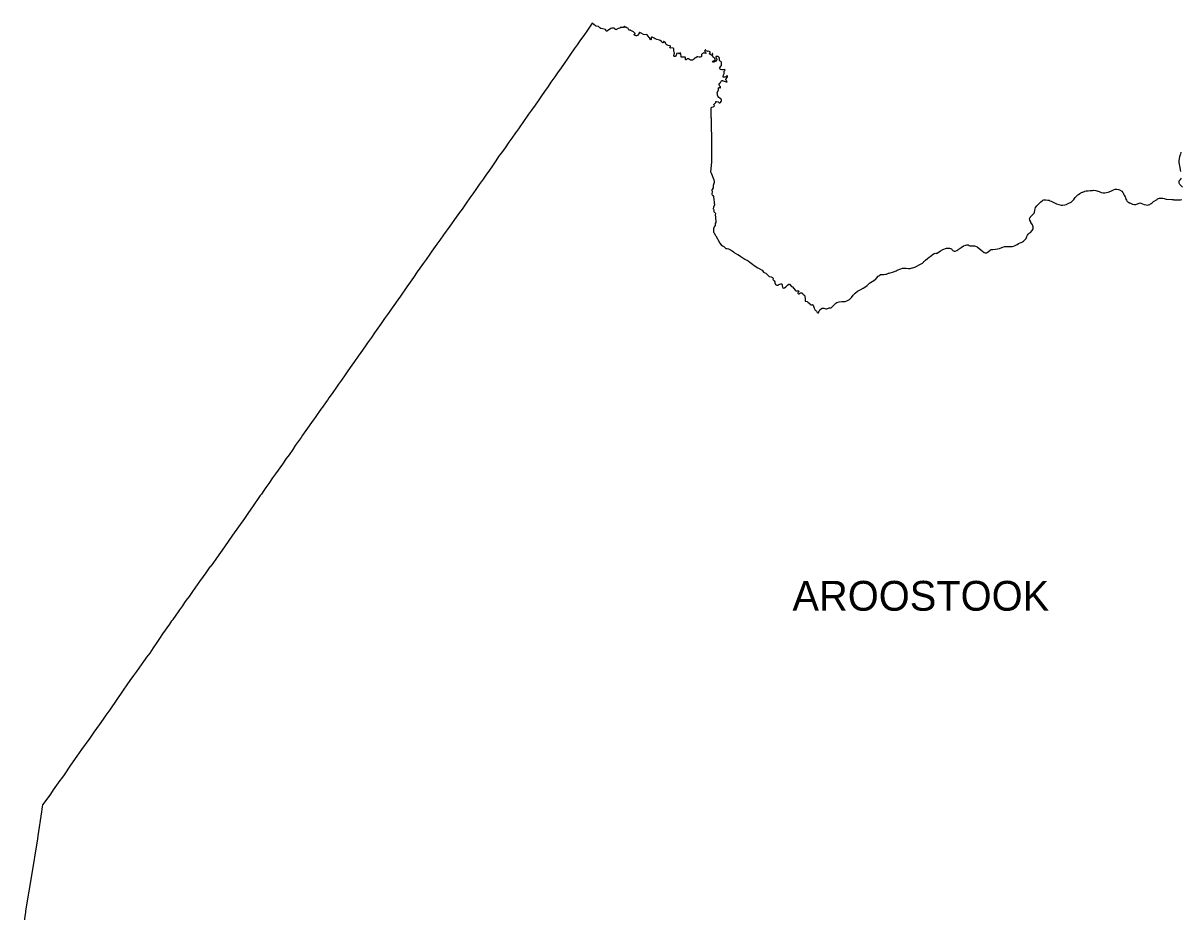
# Model space of a CAD drawing. Extents: x 1104458 to 2179854, y 15641624 to 17244911.
# Drawn here: x 1383254 to 1793637, y 16929881 to 17244911 of the extents above; entities that cross this region are included whole.
import ezdxf

# ---------------------------------------------------------------- set-up
doc = ezdxf.new("R2010")
doc.units = 0
doc.layers.add('ANNOTATION', color=7, linetype='Continuous')
doc.layers.add('CO BORDER', color=7, linetype='Continuous')

msp = doc.modelspace()

# ---------------------------------------------------------------- linework, layer by layer
at = {"layer": 'CO BORDER'}
for points in [[(1627164, 17211339), (1627163, 17214594), (1627155, 17214935), (1627355, 17215141), (1627889, 17215240), (1628089, 17215342), (1628197, 17215466), (1628272, 17215617), (1628214, 17215890), (1628123, 17216073), (1628106, 17216175), (1628173, 17216241), (1628515, 17216523), (1628748, 17216831), (1628823, 17217084), (1628999, 17217140), (1628990, 17217182), (1629615, 17217048), (1629707, 17216933), (1629715, 17216848), (1629957, 17216690), (1630107, 17216664), (1630240, 17216706), (1630473, 17216841), (1630649, 17217113), (1630774, 17217546), (1630757, 17217671), (1630699, 17217897), (1630641, 17218006), (1630225, 17218363), (1629883, 17218563), (1629542, 17219082), (1629409, 17219416), (1629392, 17219541), (1629359, 17219600), (1629334, 17219818), (1629259, 17220051), (1629276, 17220274), (1629326, 17220333), (1629685, 17221209), (1629794, 17221590), (1629794, 17221974), (1629927, 17222092), (1630069, 17222082), (1630269, 17221967), (1630444, 17221974), (1630452, 17222217), (1630402, 17222299), (1630211, 17222542), (1630103, 17222732), (1630020, 17223240), (1630045, 17223365), (1630012, 17223418), (1630070, 17223608), (1630420, 17223851), (1630629, 17224143), (1630637, 17224225), (1630654, 17224300), (1630812, 17224484), (1630996, 17224549), (1631187, 17224556), (1631362, 17224464), (1632412, 17224064), (1632695, 17224064), (1632795, 17224129), (1632754, 17224339), (1632504, 17224599), (1632371, 17224891), (1632396, 17225005), (1632471, 17225147), (1632813, 17225589), (1632972, 17225849), (1632972, 17226049), (1632930, 17226114), (1632822, 17226190), (1632722, 17226190), (1632589, 17226124), (1632355, 17225881), (1632138, 17225773), (1631938, 17225731), (1631622, 17225747), (1631438, 17225822), (1631372, 17225908), (1631364, 17226249), (1631464, 17226515), (1631539, 17226639), (1631664, 17226774), (1631722, 17226974), (1631723, 17227299), (1631715, 17227722), (1631781, 17227857), (1632048, 17228240), (1632023, 17228355), (1631949, 17228431), (1631349, 17228408), (1631040, 17228365), (1630873, 17228375), (1630473, 17228467), (1630299, 17228549), (1630165, 17228759), (1630149, 17228959), (1630199, 17229126), (1630599, 17229717), (1630699, 17229809), (1630775, 17229950), (1630800, 17230173), (1630776, 17231082), (1630742, 17231167), (1630601, 17231292), (1630326, 17231390), (1630184, 17231534), (1630151, 17231633), (1630134, 17232059), (1630060, 17232374), (1629935, 17232716), (1629769, 17232958), (1629627, 17233076), (1629427, 17233132), (1629085, 17233135), (1628844, 17233093), (1628760, 17233011), (1628760, 17232817), (1628810, 17232709), (1628993, 17232535), (1629076, 17232410), (1629135, 17232151), (1629126, 17231941), (1629059, 17231800), (1628809, 17231485), (1628300, 17231167), (1628059, 17231101), (1627851, 17231118), (1627675, 17231219), (1627684, 17231377), (1627767, 17231469), (1628209, 17231643), (1628418, 17231794), (1628534, 17231925), (1628568, 17232010), (1628568, 17232109), (1628468, 17232276), (1628460, 17232342), (1628243, 17232650), (1627993, 17232870), (1627669, 17233319), (1627661, 17233401), (1627627, 17233450), (1627719, 17233959), (1627561, 17234143), (1627444, 17234120), (1627411, 17233670), (1627344, 17233569), (1627269, 17233552), (1627077, 17233660), (1626852, 17233893), (1626678, 17233926), (1626586, 17233979), (1626811, 17234569), (1626837, 17234727), (1626778, 17234769), (1626170, 17234927), (1625886, 17234904), (1625753, 17234953), (1625362, 17235055), (1625279, 17235130), (1625154, 17235396), (1625045, 17235396), (1624962, 17235363), (1624862, 17235222), (1624837, 17235120), (1624853, 17235006), (1625170, 17234520), (1625236, 17234363), (1625194, 17234169), (1624536, 17234336), (1624361, 17234287), (1624228, 17234172), (1623994, 17234031), (1623744, 17233838), (1623677, 17233506), (1623677, 17233090), (1623627, 17232998), (1623193, 17232873), (1622943, 17232889), (1622460, 17232981), (1622168, 17232932), (1621702, 17232565), (1621276, 17232456), (1621193, 17232397), (1620884, 17232023), (1620542, 17231784), (1620326, 17231741), (1620084, 17231751), (1619876, 17231817), (1619093, 17232259), (1618885, 17232309), (1618643, 17232276), (1618301, 17231935), (1618151, 17231925), (1618068, 17231984), (1618010, 17232693), (1617927, 17232801), (1617727, 17232886), (1617018, 17232827), (1616560, 17232860), (1616518, 17232893), (1616452, 17233254), (1616444, 17233943), (1616411, 17234071), (1616203, 17234336), (1616128, 17234395), (1616044, 17234369), (1615994, 17234271), (1615944, 17234087), (1615844, 17234054), (1615677, 17234146), (1615569, 17234254), (1614953, 17234212), (1614836, 17234169), (1614827, 17233779), (1614794, 17233621), (1614735, 17233572), (1614727, 17233519), (1614535, 17233237), (1614427, 17233129), (1614319, 17233086), (1614177, 17233086), (1613952, 17233172), (1613868, 17233247), (1613852, 17233414), (1614161, 17234228), (1614153, 17234445), (1613962, 17234861), (1613895, 17235147), (1613937, 17235396), (1613887, 17235806), (1613821, 17235964), (1613729, 17236078), (1613637, 17236137), (1612796, 17236082), (1612579, 17236164), (1612521, 17236298), (1612521, 17236380), (1612671, 17236548), (1612704, 17236646), (1612688, 17236721), (1612596, 17236823), (1611896, 17237007), (1611413, 17237174), (1611313, 17237233), (1611197, 17237381), (1611114, 17237614), (1610897, 17237932), (1610539, 17238273), (1610389, 17238375), (1610280, 17238359), (1610222, 17238290), (1610164, 17238050), (1610072, 17237981), (1609947, 17237991), (1609855, 17238040), (1609838, 17238083), (1609755, 17238126), (1609709, 17238208), (1609534, 17238434), (1609019, 17238818), (1608786, 17238920), (1607928, 17239080), (1607295, 17239297), (1606954, 17239599), (1606488, 17239773), (1606205, 17239999), (1606130, 17240015), (1606005, 17239976), (1605921, 17239901), (1605879, 17239783), (1605870, 17239202), (1605836, 17239166), (1605836, 17239084), (1605794, 17239051), (1605619, 17239094), (1605404, 17239517), (1605354, 17239569), (1605279, 17239753), (1605196, 17239792), (1605179, 17239878), (1604864, 17240304), (1604415, 17240786), (1604282, 17240846), (1603648, 17240773), (1603190, 17240875), (1602299, 17241341), (1601900, 17241643), (1601708, 17241610), (1601148, 17240711), (1601006, 17240586), (1600647, 17240390), (1600531, 17240396), (1600214, 17240540), (1599989, 17240672), (1599931, 17240741), (1599890, 17240823), (1599907, 17240914), (1599999, 17241023), (1600191, 17241088), (1600182, 17241206), (1600116, 17241380), (1599850, 17241649), (1599642, 17241800), (1598910, 17242135), (1598677, 17242309), (1598519, 17242368), (1598110, 17242411), (1597911, 17242535), (1597736, 17242962), (1597728, 17243113), (1597687, 17243172), (1597237, 17243205), (1597129, 17243306), (1597129, 17243398), (1597063, 17243447), (1596604, 17243516), (1596380, 17243690), (1596313, 17243674), (1596029, 17243398), (1595504, 17243326), (1595129, 17243418), (1594954, 17243395), (1594879, 17243326), (1594879, 17243287), (1594779, 17243152), (1594670, 17243093), (1594178, 17243027), (1593986, 17242955), (1593936, 17242880), (1593744, 17242739), (1593627, 17242604), (1593536, 17242565), (1593311, 17242630), (1593169, 17242716), (1593111, 17242798), (1592737, 17243106), (1592495, 17243175), (1592204, 17243175), (1591895, 17243100), (1591595, 17242978), (1590785, 17242420), (1590184, 17242096), (1590076, 17242096), (1589951, 17242164), (1589810, 17242322), (1589761, 17242548), (1589702, 17242630), (1588203, 17243034), (1587987, 17243044), (1587687, 17243277), (1587246, 17243687), (1586330, 17243831), (1586097, 17243916), (1584927, 17244911), (1584213, 17243864), (1583259, 17242417), (1581955, 17240557), (1580851, 17239012), (1579639, 17237217), (1578618, 17235778), (1577331, 17233915), (1576343, 17232520), (1575007, 17230608), (1573961, 17229121), (1572699, 17227294), (1571686, 17225899), (1570358, 17223960), (1569345, 17222501), (1568050, 17220696), (1567013, 17219151), (1565792, 17217425), (1564696, 17215863), (1563426, 17214108), (1562430, 17212605), (1561422, 17211211)], [(1561422, 17211211), (1561085, 17210742), (1558802, 17207471), (1557814, 17206076), (1556453, 17204095), (1555414, 17202717), (1554078, 17200771), (1553165, 17199469), (1551811, 17197592), (1550857, 17196070), (1549637, 17194344), (1548582, 17192838), (1547271, 17190978), (1546274, 17189659), (1544871, 17187687), (1543941, 17186303), (1542605, 17184439), (1541550, 17182986), (1540255, 17181071), (1539309, 17179687), (1538819, 17178981)], [(1627164, 17211339), (1627269, 17201254), (1627211, 17197881), (1627236, 17195574), (1626936, 17192175), (1627019, 17192093), (1627453, 17190886), (1627894, 17189951), (1628103, 17189360), (1628244, 17188819), (1628236, 17188429), (1628061, 17188028), (1627878, 17187320), (1627878, 17187044), (1627803, 17186535), (1627470, 17185971), (1627412, 17185794), (1627445, 17184961), (1627370, 17184564), (1627370, 17184278), (1627445, 17184088), (1627745, 17183780), (1628028, 17183438), (1628103, 17182162), (1628203, 17181680), (1628253, 17181047), (1628328, 17180755), (1628336, 17180554), (1628328, 17180456), (1627912, 17179633), (1627887, 17179147), (1627942, 17179006)], [(1793666, 17192300), (1793415, 17193596), (1793379, 17193898), (1793328, 17194072), (1793129, 17195053), (1793070, 17195269), (1793055, 17196112), (1793141, 17196962), (1793311, 17197681), (1793514, 17198373), (1793588, 17198481), (1793775, 17199141)], [(1794189, 17186762), (1793258, 17187687), (1793046, 17188202), (1793043, 17188537), (1793098, 17188993), (1793337, 17189321), (1793461, 17189455), (1793824, 17189990)], [(1715417, 17165165), (1715797, 17165425), (1716620, 17165927), (1717369, 17166265), (1717743, 17166350), (1718052, 17166350), (1718219, 17166317), (1718645, 17166061), (1718803, 17166012), (1719286, 17166028), (1719612, 17165989), (1719795, 17165940), (1720453, 17165927), (1720870, 17165835), (1721380, 17165562), (1722684, 17164578), (1723921, 17163656), (1724263, 17163532), (1724447, 17163499), (1724788, 17163551), (1725312, 17163804), (1726010, 17164431), (1726134, 17164522), (1726442, 17164657), (1726892, 17164703), (1726992, 17164686), (1727900, 17164749), (1729315, 17165087), (1730139, 17165372), (1730522, 17165549), (1731129, 17165743), (1732679, 17165726), (1733629, 17165753), (1733743, 17165763), (1733826, 17165795), (1734350, 17165874), (1734916, 17166061), (1735597, 17166422), (1736104, 17166760), (1736627, 17167019), (1737027, 17167141), (1737467, 17167383), (1737849, 17167636), (1738612, 17168341), (1738763, 17168581), (1739098, 17169227), (1739296, 17169703), (1739543, 17170070), (1739850, 17170415), (1740298, 17170743), (1740928, 17171370), (1741258, 17171947), (1741289, 17172265), (1741262, 17172656), (1741016, 17173361), (1740486, 17174234), (1740435, 17174444), (1740106, 17175074), (1740038, 17175507), (1740086, 17175809), (1740267, 17176166), (1740540, 17176485), (1740731, 17176629), (1741170, 17177098), (1741419, 17177298), (1741618, 17177584), (1741733, 17177918), (1741821, 17178483), (1741886, 17178676), (1741951, 17179060), (1742082, 17179526), (1742545, 17180139), (1743548, 17181111), (1743962, 17181521), (1744601, 17182059), (1744709, 17182134), (1745058, 17182279), (1745766, 17182282), (1746534, 17182144), (1746909, 17182105), (1747168, 17181980), (1747652, 17181809), (1749574, 17180894), (1750426, 17180592), (1751186, 17180381), (1751527, 17180397), (1751719, 17180374), (1752477, 17180522), (1752984, 17180656), (1753948, 17181070), (1754729, 17181467), (1755698, 17182454), (1756204, 17183100), (1757148, 17184072), (1757322, 17184206), (1757829, 17184524), (1758045, 17184610), (1758220, 17184738), (1758701, 17184990), (1758884, 17185039), (1759150, 17185174), (1759450, 17185243), (1759624, 17185345), (1760065, 17185479), (1760374, 17185515), (1760732, 17185499), (1761448, 17185581), (1762364, 17185643), (1762681, 17185696), (1763531, 17185591), (1764207, 17185377), (1764333, 17185305), (1764649, 17185177), (1764900, 17185098), (1765343, 17184918), (1766069, 17184783), (1766744, 17184797), (1767818, 17185003), (1768807, 17185387), (1769737, 17185833), (1770369, 17186047), (1770760, 17186076), (1770902, 17186050), (1770994, 17186070), (1771520, 17185965), (1771895, 17185817), (1772699, 17185364), (1773060, 17184908), (1773137, 17184701), (1773280, 17184501), (1773365, 17184311), (1773474, 17184177), (1773551, 17183937), (1773855, 17183356), (1773969, 17183068)], [(1773969, 17183068), (1774194, 17182500), (1774347, 17182208), (1774457, 17181919), (1774583, 17181719), (1774818, 17181512), (1774911, 17181398), (1775061, 17181296), (1775187, 17181289), (1775270, 17181234), (1775512, 17181175), (1775822, 17181043), (1776523, 17180784), (1777250, 17180656), (1777708, 17180676), (1777957, 17180725), (1778639, 17181007), (1778846, 17181142), (1779062, 17181168), (1779396, 17181096), (1780616, 17180630), (1781292, 17180459), (1781885, 17180404), (1782209, 17180472), (1782633, 17180636), (1782932, 17180837), (1783106, 17180932), (1783479, 17181207), (1783960, 17181637), (1785220, 17182454), (1785419, 17182631), (1786092, 17182884), (1786325, 17182861), (1786750, 17182881), (1786984, 17182884), (1787117, 17182825), (1787276, 17182818), (1787718, 17182697), (1788394, 17182575), (1790487, 17182457), (1790912, 17182411), (1791113, 17182339), (1791872, 17182260), (1792522, 17182274), (1793097, 17182244), (1793538, 17182280), (1793996, 17182359)], [(1538819, 17178981), (1537981, 17177774), (1536793, 17176110), (1534544, 17172938), (1532293, 17169847), (1530907, 17168036), (1529902, 17166507), (1528117, 17164043), (1527362, 17162977), (1526066, 17161130), (1525003, 17159660), (1523899, 17158016), (1522945, 17156704), (1521608, 17154752), (1519300, 17151484), (1516967, 17148154), (1516042, 17146802)], [(1627942, 17179006), (1628037, 17178763), (1628112, 17178465), (1628078, 17178189), (1628095, 17178107), (1628212, 17177864), (1628395, 17177841), (1628553, 17177723), (1628620, 17177631), (1628653, 17177431), (1628603, 17176867), (1628620, 17176690), (1628687, 17176489), (1628736, 17176181), (1628703, 17175492), (1628803, 17174941), (1628812, 17174659), (1628745, 17174291), (1628570, 17173943), (1628512, 17173760), (1628537, 17173635), (1628512, 17173149), (1628212, 17172700), (1627995, 17172008), (1627920, 17171502), (1627979, 17171210), (1627996, 17170853), (1628062, 17170659), (1628570, 17169819), (1628720, 17169603), (1628804, 17169570), (1629337, 17168510), (1629537, 17168202), (1630270, 17166962), (1630711, 17166371), (1631186, 17165955), (1631627, 17165705), (1632177, 17165121), (1632352, 17165019), (1632519, 17164980), (1632777, 17164987), (1633335, 17164928), (1633568, 17164819), (1634618, 17164170), (1635051, 17163796), (1635451, 17163546), (1635917, 17163205), (1636025, 17163179), (1636592, 17162870), (1637208, 17162513), (1637666, 17162198), (1638050, 17161988), (1638716, 17161463), (1639049, 17161263), (1639599, 17161056), (1640049, 17160823), (1640265, 17160639), (1640898, 17160213), (1641835, 17159471), (1642435, 17159025), (1643739, 17158205), (1644163, 17157929), (1644993, 17157473), (1645216, 17157326), (1645736, 17156607), (1645901, 17156492), (1646482, 17156299), (1646698, 17156158), (1647039, 17155758), (1647188, 17155541), (1647421, 17155292), (1647646, 17155151), (1648403, 17154934), (1648844, 17154711), (1648986, 17154576), (1649069, 17154261), (1649061, 17154028), (1649111, 17153878), (1649194, 17153753), (1649485, 17153536), (1649669, 17153162), (1649744, 17152838), (1649986, 17152277), (1650161, 17152112), (1650411, 17151994), (1650835, 17152080), (1651110, 17152247), (1651452, 17152345), (1651785, 17152503), (1651960, 17152546), (1652093, 17152539), (1652218, 17152464), (1652302, 17152296), (1652318, 17152037), (1652293, 17151889), (1652386, 17151305), (1652494, 17151131), (1652594, 17151046), (1652827, 17150981), (1653194, 17151105), (1653593, 17151430), (1654185, 17152007), (1654718, 17152375), (1654793, 17152408), (1654926, 17152359), (1655668, 17151607), (1655960, 17151391), (1656477, 17150899), (1656869, 17150200), (1657102, 17150042), (1657586, 17149993), (1657969, 17149993), (1658102, 17149967), (1658261, 17149875), (1658269, 17149783), (1658128, 17149511), (1657828, 17149311), (1657820, 17149209), (1657945, 17149084), (1658111, 17148986), (1658236, 17148950), (1658411, 17148976), (1658511, 17149025), (1658695, 17149235), (1658786, 17149301), (1659094, 17149317), (1659228, 17149278), (1659586, 17148960), (1659678, 17148835), (1660020, 17148651), (1660153, 17148543), (1660320, 17148277), (1660421, 17146919), (1660413, 17146512), (1660446, 17146387), (1661163, 17146194), (1661572, 17145928), (1661897, 17145636), (1662281, 17145223), (1662556, 17145088), (1662706, 17145055), (1662939, 17145088), (1663031, 17145147), (1663122, 17145154), (1663214, 17145114), (1663298, 17144921), (1663648, 17143832), (1664057, 17143129), (1664207, 17142998), (1664441, 17142857), (1664758, 17142372), (1664975, 17142263), (1665175, 17142257), (1665316, 17142506), (1665349, 17142700), (1665432, 17142755), (1665665, 17143290), (1666198, 17143733), (1666432, 17143848), (1666748, 17143907), (1667048, 17143884), (1667807, 17143618), (1668124, 17143667), (1668998, 17143943), (1669448, 17143976), (1669666, 17144015)], [(1683583, 17152974), (1684255, 17153367), (1685121, 17153905), (1685245, 17153997), (1685412, 17154073), (1685919, 17154581), (1686351, 17155192), (1686575, 17155392), (1686916, 17155634), (1687166, 17155769), (1687291, 17155769), (1687433, 17155808), (1688033, 17155835), (1688391, 17155805), (1688932, 17155881), (1689307, 17155982), (1690032, 17156241), (1690240, 17156274), (1691813, 17156802), (1692679, 17157163), (1693054, 17157347), (1694394, 17157859), (1695010, 17158030), (1696227, 17158023), (1697110, 17157934), (1697702, 17157944), (1698352, 17158128), (1698551, 17158161), (1699001, 17158305), (1699301, 17158463), (1699758, 17158646), (1701398, 17159486), (1702072, 17159887), (1702438, 17160238), (1702546, 17160464), (1702717, 17160546), (1703099, 17160923), (1703771, 17161511), (1703904, 17161576), (1704286, 17161888), (1704926, 17162321), (1705508, 17162724), (1705649, 17162859), (1705882, 17162994), (1706214, 17163236), (1706539, 17163338), (1706881, 17163312), (1707064, 17163338), (1707230, 17163397), (1708427, 17164221), (1709242, 17164624), (1710557, 17165120), (1710898, 17165179), (1711607, 17165149), (1712283, 17164910), (1712508, 17164719), (1712709, 17164454), (1712868, 17164322), (1713269, 17164106), (1713678, 17164089), (1714177, 17164283), (1714592, 17164585), (1714875, 17164752), (1715116, 17164962), (1715417, 17165165)], [(1669666, 17144015), (1669731, 17144028), (1670322, 17144612), (1670847, 17145213), (1671280, 17145603), (1671699, 17145879), (1672540, 17146181), (1673457, 17146250), (1673948, 17146250), (1674590, 17146286), (1675289, 17146479), (1675913, 17146804), (1676129, 17147007), (1676271, 17147083), (1676928, 17147716), (1677509, 17148443), (1677700, 17148718), (1678149, 17149220), (1678989, 17149857), (1679988, 17150424), (1681020, 17150953), (1682018, 17151579), (1682501, 17151924), (1683149, 17152567), (1683307, 17152751), (1683583, 17152974)], [(1516042, 17146802), (1514667, 17144863), (1512400, 17141615), (1511371, 17140188), (1510126, 17138433), (1507826, 17135168), (1506713, 17133525), (1505343, 17131579), (1504356, 17130132), (1502936, 17128170), (1501998, 17126884), (1500669, 17124988), (1499756, 17123620), (1498378, 17121674), (1497415, 17120286), (1496061, 17118357), (1495040, 17116881), (1493802, 17115139)], [(1493802, 17115139), (1493479, 17114692), (1493239, 17114309), (1492757, 17113665), (1491636, 17112055), (1491088, 17111320), (1490657, 17110644), (1489345, 17108839), (1488814, 17108039), (1486987, 17105499), (1486182, 17104312), (1485733, 17103669), (1484637, 17102174), (1482329, 17098900), (1481748, 17098057), (1481134, 17097095), (1479714, 17095143), (1478801, 17093788), (1477506, 17091895), (1476543, 17090540), (1475140, 17088536), (1472690, 17085130), (1471679, 17083706)], [(1471679, 17083706), (1470308, 17081665), (1469336, 17080310), (1468381, 17078932), (1467991, 17078325), (1467701, 17077915), (1467322, 17077417), (1464513, 17073394), (1463132, 17071429), (1461667, 17069362), (1457481, 17063417), (1454575, 17059254), (1451771, 17055215), (1450499, 17053374), (1449600, 17052147)], [(1427130, 17020126), (1428223, 17021629), (1429478, 17023446), (1430742, 17025362), (1431728, 17026806), (1432781, 17028397), (1435215, 17031888), (1435990, 17032990), (1436394, 17033486), (1437489, 17035047), (1438364, 17036274), (1438803, 17036944), (1439822, 17038387), (1440604, 17039483), (1441169, 17040310), (1442171, 17041721), (1443434, 17043463), (1445868, 17046934), (1447148, 17048732), (1448117, 17050110), (1449600, 17052147)], [(1404101, 16987486), (1406984, 16991499), (1408474, 16993598), (1410334, 16996133), (1411775, 16998206), (1412718, 16999548), (1414041, 17001504), (1418784, 17008413), (1420173, 17010336), (1421243, 17011894), (1422497, 17013686), (1423525, 17015136), (1426076, 17018627), (1426665, 17019473), (1427130, 17020126)], [(1388418, 16955755), (1388584, 16956803), (1389840, 16965330), (1389997, 16966239), (1390145, 16967138), (1390275, 16967811), (1391715, 16969802), (1393020, 16971633), (1394056, 16973152), (1396422, 16976426), (1396953, 16977181), (1397862, 16978490), (1400205, 16981922), (1402411, 16985114), (1404101, 16987486)], [(1383254, 16923497), (1384187, 16929764), (1384217, 16930121), (1384587, 16932392), (1386257, 16942082), (1388418, 16955755)]]:
    msp.add_lwpolyline(points, dxfattribs=at)

# ---------------------------------------------------------------- texts
at = {"layer": 'ANNOTATION'}
msp.add_text('AROOSTOOK', height=10560.2, dxfattribs=at).set_placement((1655951, 17036632))

doc.saveas('drawing.dxf')
